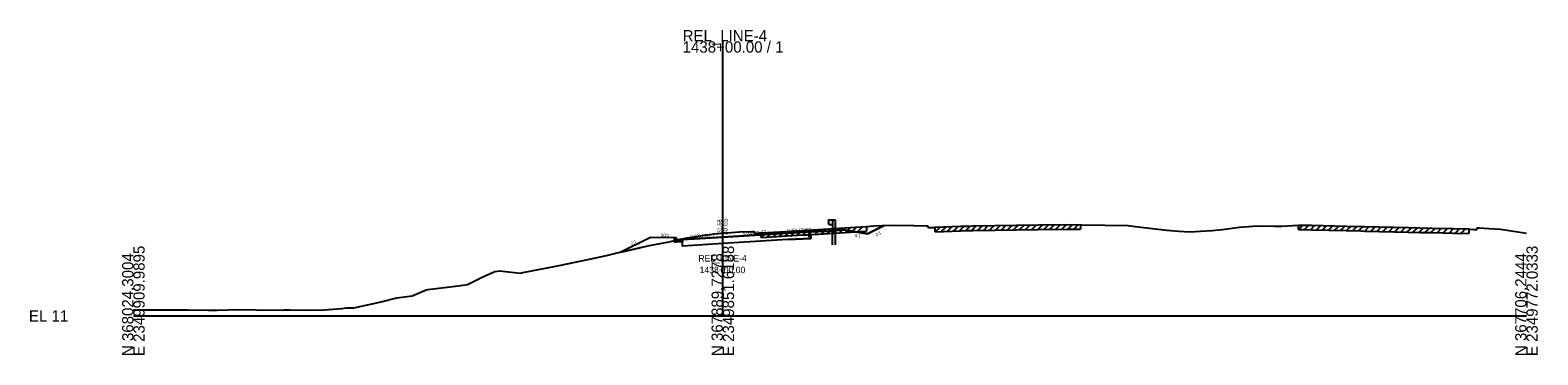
# Model space of a CAD drawing. Extents: x -26 to 2350146, y -10 to 368200.
# Drawn here: x 1974.3 to 2349.5, y -9.7 to 71.2 of the extents above; entities that cross this region are included whole.
import ezdxf

# ---------------------------------------------------------------- set-up
doc = ezdxf.new("R2010")
doc.units = 0
for name, color, linetype in [('RD_GPK_XS_Cell', 7, 'Continuous'), ('RD_XS_Base', 7, 'Continuous'), ('RD_XS_CurbBase', 7, 'Continuous'), ('RD_XS_CurbFront', 7, 'Continuous'), ('RD_XS_CurbTop', 7, 'Continuous'), ('RD_XS_Ditch', 7, 'Continuous'), ('RD_XS_EarthShd', 7, 'Continuous'), ('RD_XS_EwShp', 7, 'Continuous'), ('RD_XS_ExGround', 7, 'Continuous'), ('RD_XS_ExPaveRet', 7, 'Continuous'), ('RD_XS_GR', 7, 'Continuous'), ('RD_XS_Pave', 7, 'Continuous'), ('RD_XS_PaveShd', 7, 'Continuous'), ('RD_XS_TieSlope', 7, 'Continuous'), ('RD_XS_TX_Elev_EX', 7, 'Continuous'), ('RD_XS_TX_Elev_PR', 7, 'Continuous'), ('RD_XS_TX_Slope', 7, 'Continuous'), ('RD_XS_TX_Station', 7, 'Continuous')]:
    doc.layers.add(name, color=color, linetype=linetype)

msp = doc.modelspace()

# ---------------------------------------------------------------- linework, layer by layer
at = {"layer": 'RD_GPK_XS_Cell'}
for p, q in [((2146.69, 0), (2146.69, 68.36)), ((2000, 0), (2146.69, 0)), ((2146.69, 0), (2346.69, 0))]:
    msp.add_line(p, q, dxfattribs=at)
at = {"layer": 'RD_XS_Base'}
for p, q in [((2162.79, 18.99), (2146.79, 18.02)), ((2162.77, 18.99), (2168.63, 19.28)), ((2168.13, 20.9), (2168.13, 19.76)), ((2168.13, 19.76), (2168.63, 19.78)), ((2168.63, 19.28), (2168.63, 19.78)), ((2136.69, 17.41), (2136.69, 18.53)), ((2146.79, 18.02), (2136.69, 17.41))]:
    msp.add_line(p, q, dxfattribs=at)
at = {"layer": 'RD_XS_CurbBase'}
for p, q in [((2134.69, 19.44), (2134.69, 18.44)), ((2134.69, 18.44), (2135.19, 18.44)), ((2135.19, 18.44), (2136.69, 18.53))]:
    msp.add_line(p, q, dxfattribs=at)
at = {"layer": 'RD_XS_CurbFront'}
msp.add_line((2136.69, 18.53), (2136.69, 19.03), dxfattribs=at)
at = {"layer": 'RD_XS_CurbTop'}
for p, q in [((2135.19, 19.44), (2134.69, 19.44)), ((2135.27, 18.94), (2135.19, 19.44)), ((2136.69, 19.03), (2135.27, 18.94)), ((2136.69, 19.05), (2136.69, 19.03))]:
    msp.add_line(p, q, dxfattribs=at)
at = {"layer": 'RD_XS_Ditch'}
for p, q in [((2182.69, 20.44), (2186.88, 22.54)), ((2176.69, 21.44), (2182.69, 20.44))]:
    msp.add_line(p, q, dxfattribs=at)
at = {"layer": 'RD_XS_EarthShd'}
for p, q in [((2134.69, 19.44), (2128.69, 19.56)), ((2168.13, 20.9), (2172.94, 21.14))]:
    msp.add_line(p, q, dxfattribs=at)
at = {"layer": 'RD_XS_EwShp'}
for points in [[(2135.27, 18.94), (2137.82, 19.42), (2144.52, 20.41), (2146.69, 20.58), (2150.87, 20.9), (2153.84, 21.05), (2154.39, 21.06), (2154.56, 20.56), (2155.8, 20.65), (2156.21, 20.68), (2163.96, 21.14), (2166.78, 21.31), (2167.14, 21.33), (2167.66, 21.36), (2170.38, 21.51), (2182.45, 22.23), (2184.28, 22.4), (2186.88, 22.54), (2182.69, 20.44), (2176.69, 21.44), (2172.94, 21.14), (2168.13, 20.9), (2162.69, 20.62), (2146.69, 19.65), (2136.69, 19.03)], [(2121.34, 15.89), (2128.43, 17.5), (2133.35, 18.46), (2134.69, 18.75), (2134.69, 19.44), (2128.69, 19.56)], [(2134.69, 18.75), (2135.27, 18.94), (2136.69, 19.03), (2136.69, 18.53), (2135.19, 18.44), (2134.69, 18.44)], [(2162.77, 18.99), (2146.79, 18.02), (2136.69, 17.41), (2136.69, 18.53), (2136.69, 19.03), (2146.69, 19.65), (2162.69, 20.62), (2168.13, 20.9), (2168.13, 19.76), (2168.63, 19.78), (2168.63, 19.28)]]:
    msp.add_lwpolyline(points, close=True, dxfattribs=at)
at = {"layer": 'RD_XS_ExGround'}
msp.add_lwpolyline([(2000, 1.52), (2003.7, 1.49), (2010.12, 1.54), (2013.64, 1.51), (2018.68, 1.46), (2019.89, 1.47), (2020.82, 1.41), (2026.2, 1.58), (2030.55, 1.51), (2037.01, 1.41), (2037.61, 1.49), (2038.92, 1.48), (2043.8, 1.44), (2047.47, 1.52), (2051.89, 1.88), (2053.06, 1.99), (2054.89, 2), (2061.64, 3.5), (2065.6, 4.51), (2069.34, 5.02), (2072.86, 6.51), (2073.26, 6.55), (2080.84, 7.49), (2083.17, 7.79), (2086.81, 9.66), (2089.94, 11.08), (2091.17, 11.19), (2096.23, 10.67), (2096.9, 10.81), (2105.12, 12.39), (2105.93, 12.56), (2113.53, 14.17), (2117.77, 15.06), (2121.1, 15.84), (2128.43, 17.5), (2133.35, 18.46), (2137.82, 19.42), (2144.52, 20.41), (2146.69, 20.58), (2150.87, 20.9), (2153.84, 21.05), (2154.39, 21.06), (2154.56, 20.56), (2155.8, 20.65), (2156.21, 20.68), (2163.96, 21.14), (2166.78, 21.31), (2167.14, 21.33), (2167.66, 21.36), (2170.38, 21.51), (2182.45, 22.23), (2184.28, 22.4), (2188.34, 22.61), (2194.24, 22.5), (2197.27, 22.45), (2197.66, 22.43), (2197.81, 22), (2198.92, 22.02), (2199.42, 22.03), (2199.56, 22.08), (2205.86, 22.32), (2207.62, 22.38), (2208.96, 22.41), (2219.8, 22.61), (2225.22, 22.69), (2232.38, 22.79), (2235.73, 22.72), (2236.03, 22.71), (2247.55, 22.49), (2249.29, 22.29), (2257.23, 21.39), (2260.19, 21.12), (2262.9, 20.95), (2265.59, 21.08), (2268.49, 21.27), (2271.05, 21.54), (2275.29, 22.11), (2278.56, 22.37), (2280.9, 22.47), (2283.99, 22.34), (2285.83, 22.39), (2289.93, 22.62), (2291.79, 22.62), (2293.19, 22.61), (2301.8, 22.39), (2305.48, 22.29), (2306.51, 22.27), (2317.34, 21.98), (2320.09, 21.93), (2323.16, 21.88), (2328.55, 21.76), (2332.38, 21.66), (2332.59, 21.58), (2333.57, 21.54), (2334.31, 21.5), (2334.53, 21.96), (2334.93, 21.97), (2337.34, 21.78), (2340.27, 21.6), (2342.36, 21.28), (2346.69, 20.61)], dxfattribs=at)
at = {"layer": 'RD_XS_ExPaveRet'}
for p, q in [((2214.56, 21.37), (2215.72, 22.54)), ((2216.06, 21.4), (2217.22, 22.56)), ((2217.56, 21.43), (2218.72, 22.59)), ((2219.06, 21.46), (2220.22, 22.62)), ((2220.56, 21.48), (2221.72, 22.64)), ((2222.06, 21.5), (2223.22, 22.66)), ((2223.56, 21.52), (2224.72, 22.68)), ((2225.06, 21.54), (2226.22, 22.7)), ((2226.56, 21.56), (2227.72, 22.72)), ((2228.06, 21.58), (2229.22, 22.74)), ((2229.56, 21.6), (2230.72, 22.76)), ((2231.06, 21.63), (2232.22, 22.78)), ((2232.56, 21.64), (2233.68, 22.76)), ((2234.06, 21.61), (2235.18, 22.73)), ((2235.73, 22.72), (2235.73, 21.57)), ((2289.93, 21.48), (2291.07, 22.62)), ((2289.93, 21.48), (2289.93, 22.62)), ((2291.43, 21.48), (2292.57, 22.62)), ((2292.93, 21.47), (2294.05, 22.59)), ((2294.43, 21.44), (2295.54, 22.55)), ((2156.21, 19.54), (2157.43, 20.75)), ((2156.21, 19.54), (2156.21, 20.68)), ((2156.21, 19.54), (2163.96, 20)), ((2157.71, 19.63), (2158.93, 20.84)), ((2159.21, 19.72), (2160.43, 20.93)), ((2160.71, 19.81), (2161.93, 21.02)), ((2162.21, 19.9), (2163.43, 21.11)), ((2163.71, 19.99), (2164.93, 21.2)), ((2163.96, 20), (2166.78, 20.17)), ((2165.21, 20.07), (2166.43, 21.29)), ((2166.71, 20.16), (2167.92, 21.37)), ((2166.78, 20.17), (2167.14, 20.19)), ((2167.14, 20.19), (2167.66, 20.21)), ((2167.66, 20.21), (2170.38, 20.36)), ((2168.21, 20.24), (2169.42, 21.45)), ((2169.71, 20.33), (2170.92, 21.54)), ((2170.38, 20.36), (2182.45, 21.09)), ((2171.21, 20.41), (2172.43, 21.63)), ((2172.71, 20.5), (2173.93, 21.72)), ((2174.21, 20.59), (2175.43, 21.81)), ((2175.71, 20.68), (2176.93, 21.9)), ((2177.21, 20.77), (2178.43, 21.99)), ((2178.71, 20.86), (2179.93, 22.08)), ((2180.21, 20.95), (2181.43, 22.17)), ((2182.45, 22.23), (2182.45, 21.09)), ((2199.56, 20.94), (2200.75, 22.12)), ((2199.56, 20.94), (2199.56, 22.08)), ((2199.56, 20.94), (2205.86, 21.18)), ((2201.06, 20.99), (2202.25, 22.18)), ((2202.56, 21.05), (2203.75, 22.24)), ((2204.06, 21.11), (2205.25, 22.3)), ((2205.56, 21.16), (2206.74, 22.35)), ((2205.86, 21.18), (2207.62, 21.24)), ((2207.06, 21.22), (2208.23, 22.39)), ((2207.62, 21.24), (2208.96, 21.26)), ((2208.56, 21.26), (2209.72, 22.42)), ((2208.96, 21.26), (2219.8, 21.47)), ((2210.06, 21.28), (2211.22, 22.45)), ((2211.56, 21.31), (2212.72, 22.48)), ((2213.06, 21.34), (2214.22, 22.51)), ((2219.8, 21.47), (2225.22, 21.54)), ((2225.22, 21.54), (2232.38, 21.64)), ((2232.38, 21.64), (2235.73, 21.57)), ((2289.93, 21.48), (2291.79, 21.48)), ((2291.79, 21.48), (2293.19, 21.47)), ((2293.19, 21.47), (2301.8, 21.25)), ((2295.93, 21.4), (2297.04, 22.51)), ((2297.43, 21.36), (2298.54, 22.47)), ((2298.93, 21.32), (2300.04, 22.43)), ((2300.43, 21.28), (2301.54, 22.4)), ((2301.8, 21.25), (2305.48, 21.15)), ((2301.93, 21.24), (2303.04, 22.36)), ((2303.43, 21.2), (2304.54, 22.32)), ((2304.93, 21.17), (2306.04, 22.28)), ((2305.48, 21.15), (2306.51, 21.12)), ((2306.43, 21.13), (2307.54, 22.24)), ((2306.51, 21.12), (2317.34, 20.83)), ((2307.93, 21.09), (2309.04, 22.2)), ((2309.43, 21.05), (2310.54, 22.16)), ((2310.93, 21.01), (2312.04, 22.12)), ((2312.43, 20.97), (2313.54, 22.08)), ((2313.93, 20.92), (2315.04, 22.04)), ((2315.43, 20.88), (2316.54, 22)), ((2316.93, 20.84), (2318.05, 21.97)), ((2317.34, 20.83), (2320.09, 20.79)), ((2318.43, 20.82), (2319.55, 21.94)), ((2319.93, 20.79), (2321.05, 21.92)), ((2320.09, 20.79), (2323.16, 20.74)), ((2321.43, 20.77), (2322.55, 21.89)), ((2322.93, 20.74), (2324.05, 21.86)), ((2323.16, 20.74), (2328.55, 20.61)), ((2324.43, 20.71), (2325.55, 21.83)), ((2325.93, 20.67), (2327.05, 21.79)), ((2327.43, 20.64), (2328.55, 21.76)), ((2328.55, 20.61), (2332.38, 20.52)), ((2328.93, 20.6), (2330.04, 21.72)), ((2330.43, 20.57), (2331.54, 21.68)), ((2332.38, 21.66), (2332.38, 20.52))]:
    msp.add_line(p, q, dxfattribs=at)
at = {"layer": 'RD_XS_GR'}
for p, q in [((2173.1, 23.89), (2172.93, 23.69)), ((2172.93, 23.69), (2172.93, 23.64)), ((2172.93, 23.64), (2173.1, 23.44)), ((2172.93, 23.11), (2173.1, 23.31)), ((2172.93, 23.06), (2172.93, 23.11)), ((2173.1, 22.86), (2172.93, 23.06)), ((2173.1, 23.96), (2174.01, 23.96)), ((2173.1, 22.79), (2173.1, 23.96)), ((2173.1, 22.79), (2174.01, 22.79)), ((2174.01, 23.96), (2174.68, 23.96)), ((2174.01, 23.96), (2174.01, 21.21)), ((2174.68, 23.96), (2174.68, 21.16)), ((2174.01, 17.74), (2174.01, 21.21)), ((2174.68, 21.16), (2174.68, 17.74))]:
    msp.add_line(p, q, dxfattribs=at)
at = {"layer": 'RD_XS_Pave'}
for p, q in [((2146.69, 19.65), (2136.69, 19.05)), ((2162.69, 20.62), (2146.69, 19.65))]:
    msp.add_line(p, q, dxfattribs=at)
at = {"layer": 'RD_XS_PaveShd'}
msp.add_line((2162.69, 20.62), (2168.13, 20.9), dxfattribs=at)
at = {"layer": 'RD_XS_TieSlope'}
for p, q in [((2128.69, 19.56), (2121.34, 15.89)), ((2172.94, 21.14), (2176.69, 21.44))]:
    msp.add_line(p, q, dxfattribs=at)

# ---------------------------------------------------------------- texts
at = {"layer": 'RD_GPK_XS_Cell'}
for s, p in [('1438+00.00 / 1', (2136.69, 65.56)), ('REL_LINE-4', (2136.69, 68.36)), ('EL 11', (1974, -1.4))]:
    msp.add_text(s, height=2.8, dxfattribs=at).set_placement(p)
for s, p in [('N 368024.3004', (2000, -10)), ('E 2349909.9895', (2002.8, -10)), ('N 367889.7278', (2146.69, -10)), ('E 2349851.6188', (2149.49, -10)), ('N 367706.2444', (2346.69, -10)), ('E 2349772.0333', (2349.49, -10))]:
    msp.add_text(s, height=2.8, rotation=90, dxfattribs=at).set_placement(p)
at = {"layer": 'RD_XS_TX_Elev_EX'}
msp.add_text('31.58', height=1, rotation=90, dxfattribs=at).set_placement((2146.34, 20.58))
at = {"layer": 'RD_XS_TX_Elev_PR'}
msp.add_text(' 30.65', height=1.2, rotation=90, dxfattribs=at).set_placement((2147.89, 19.65))
at = {"layer": 'RD_XS_TX_Slope'}
for s, rotation, p in [('2:1', 26.5651, (2123.97, 17.69)), ('50:1', 358.8542, (2131.32, 19.73)), ('0.060 FT./FT.', 3.4586, (2138.65, 19.42)), ('0.060 FT./FT.', 3.4593, (2151.65, 20.2)), ('0.051 FT./FT.', 2.8986, (2162.77, 20.87)), ('6:1', 350.5377, (2179.54, 19.73)), ('2:1', 26.5651, (2184.89, 19.83))]:
    msp.add_text(s, height=0.75, rotation=rotation, dxfattribs=at).set_placement(p)
at = {"layer": 'RD_XS_TX_Station'}
for s, p in [('REL_LINE-4', (2140.62, 13.55)), ('1438+00.00', (2140.92, 10.65))]:
    msp.add_text(s, height=1.6, dxfattribs=at).set_placement(p)

doc.saveas('drawing.dxf')
